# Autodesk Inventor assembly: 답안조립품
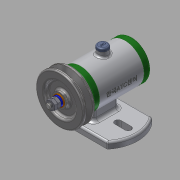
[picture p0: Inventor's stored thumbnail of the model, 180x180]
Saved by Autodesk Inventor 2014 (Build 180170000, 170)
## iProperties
Created: 2017-12
Part Number: 답안조립품
Document SubType Name: Assembly
Designer: user
Author: user
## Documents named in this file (14)
- C:\Users\user\Desktop\471208V1002\답안조립품.iam
- C:\Users\user\Desktop\471208V1002\축.ipt
- C:\Users\user\Desktop\471208V1002\베어링 15 x 32 x 9.ipt
- C:\Users\user\Desktop\471208V1002\키 3 x 3 x 12.ipt
- C:\Users\user\Desktop\471208V1002\본체.ipt
- C:\Users\user\Desktop\471208V1002\V벨트풀리.ipt
- C:\Users\user\Desktop\471208V1002\고무캡.ipt
- C:\Users\user\Desktop\471208V1002\너트 M 8.ipt
- C:\Users\user\Desktop\471208V1002\스프링와셔 8.ipt
- C:\Users\user\Desktop\471208V1002\와셔 8x17.ipt
- C:\Users\user\Desktop\471208V1002\뒤커버.ipt
- C:\Users\user\Desktop\471208V1002\앞커버.ipt
- C:\Users\user\Desktop\471208V1002\오일 실 15 25 7.ipt
- C:\Users\user\Desktop\471208V1002\볼트 M4 x 12.ipt
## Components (2 placed, 2 different names)
1. V벨트풀리:1 — 각도:1
2. 고무캡:1
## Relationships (1: Angle 1)
- 각도:1 [Angle]: V벨트풀리:1
